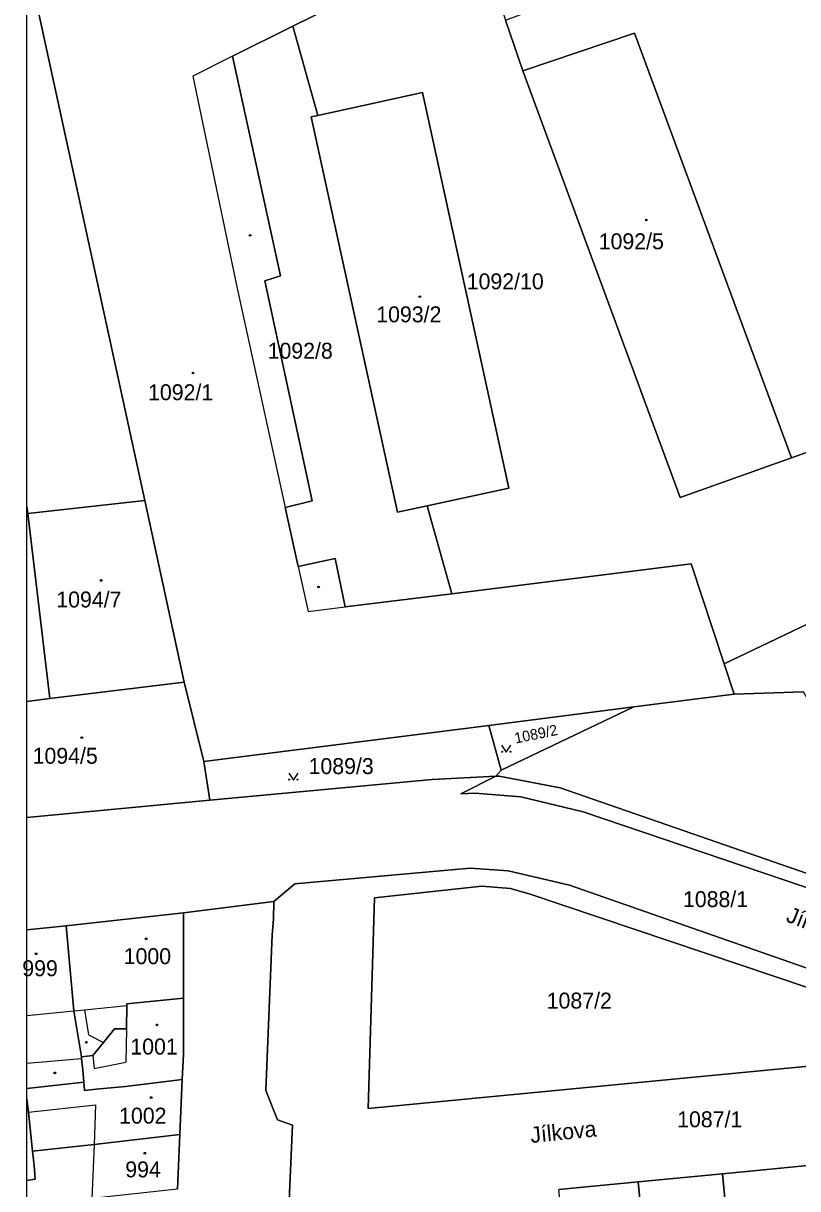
# Model space of a CAD drawing. Extents: x -596233 to -595156, y -1161235 to -1159375.
# Drawn here: x -596228.6 to -596146, y -1160887.6 to -1160763.3 of the extents above; entities that cross this region are included whole.
import ezdxf

# ---------------------------------------------------------------- set-up
doc = ezdxf.new("R2010")
doc.units = 0
for name, color, linetype in [('KN_CAR_KR', 7, 'Continuous'), ('KN_KULTURY', 7, 'Continuous'), ('KN_PARC_CIS_POZ', 7, 'Continuous'), ('KN_PARC_CIS_STAV', 7, 'Continuous'), ('KN_PARC_PLOCHA', 7, 'Continuous'), ('KN_ULICE', 7, 'Continuous'), ('parcely_l', 7, 'Continuous')]:
    doc.layers.add(name, color=color, linetype=linetype)

msp = doc.modelspace()

# ---------------------------------------------------------------- linework, layer by layer
at = {"layer": 'KN_CAR_KR'}
for points in [[(-596206.28, -1160766.77), (-596210.51, -1160768.91)], [(-596210.51, -1160768.91), (-596205.83, -1160791.38)], [(-596205.83, -1160791.38), (-596200.64, -1160814.91)], [(-596199.26, -1160821.19), (-596198.19, -1160826.01)], [(-596198.19, -1160826.01), (-596194.26, -1160825.52)], [(-596228.2196, -1160869.0741), (-596223.22, -1160868.58)], [(-596223.22, -1160868.58), (-596222.08, -1160868.47)], [(-596222.08, -1160868.47), (-596217.55, -1160868.01)], [(-596222.08, -1160868.47), (-596221.63, -1160871.15)], [(-596217.59, -1160870.52), (-596217.65, -1160874.08)], [(-596221.63, -1160871.15), (-596220.05, -1160871.97)], [(-596221.17, -1160873.36), (-596221.03, -1160874.75)], [(-596228.2196, -1160874.1739), (-596222.38, -1160873.66)], [(-596221.03, -1160874.75), (-596217.65, -1160874.08)], [(-596228.06, -1160879.39), (-596220.89, -1160878.61)], [(-596220.89, -1160878.61), (-596221.05, -1160882.84)], [(-596221.05, -1160882.84), (-596221.27, -1160888.59)]]:
    msp.add_lwpolyline(points, dxfattribs=at)
at = {"layer": 'KN_KULTURY'}
for points in [[(-596177.5618, -1160840.2616), (-596177.0618, -1160841.0116), (-596176.5618, -1160840.2616)], [(-596200.2818, -1160843.2316), (-596199.7818, -1160843.9816), (-596199.2818, -1160843.2316)]]:
    msp.add_lwpolyline(points, dxfattribs=at)
for centre, radius in [((-596162.12, -1160784.25), 0.09), ((-596162.12, -1160784.25), 0.0398), ((-596204.39, -1160785.89), 0.09), ((-596204.39, -1160785.89), 0.0398), ((-596186.29, -1160792.43), 0.09), ((-596186.29, -1160792.43), 0.0398), ((-596210.49, -1160800.57), 0.09), ((-596210.49, -1160800.57), 0.0398), ((-596220.3, -1160822.69), 0.09), ((-596220.3, -1160822.69), 0.0398), ((-596197.09, -1160823.39), 0.09), ((-596197.09, -1160823.39), 0.0398), ((-596222.36, -1160839.45), 0.09), ((-596222.36, -1160839.45), 0.0398), ((-596177.512, -1160840.9614), 0.05), ((-596176.6126, -1160840.9614), 0.05), ((-596200.232, -1160843.9314), 0.05), ((-596199.3326, -1160843.9314), 0.05), ((-596215.48, -1160860.91), 0.09), ((-596215.48, -1160860.91), 0.0398), ((-596227.23, -1160862.51), 0.09), ((-596227.23, -1160862.51), 0.0398), ((-596214.33, -1160870.09), 0.09), ((-596214.33, -1160870.09), 0.0398), ((-596221.87, -1160871.95), 0.09), ((-596221.87, -1160871.95), 0.0398), ((-596225.23, -1160875.21), 0.09), ((-596225.23, -1160875.21), 0.0398), ((-596214.95, -1160877.84), 0.09), ((-596214.95, -1160877.84), 0.0398), ((-596215.64, -1160883.78), 0.09), ((-596215.64, -1160883.78), 0.0398)]:
    msp.add_circle(centre, radius, dxfattribs=at)
at = {"layer": 'KN_PARC_PLOCHA'}
for points in [[(-596180.21, -1160753.92), (-596199.82, -1160763.59), (-596206.28, -1160766.77), (-596201.14, -1160790.21), (-596202.84, -1160790.73), (-596197.78, -1160814.19), (-596200.64, -1160814.91), (-596199.26, -1160821.19), (-596195.33, -1160820.35), (-596194.26, -1160825.52), (-596182.87, -1160824.1), (-596157.33, -1160820.92), (-596153.81, -1160831.58), (-596152.74, -1160834.82), (-596163.44, -1160836.18), (-596178.93, -1160838.15), (-596209.35, -1160842.01), (-596211.43, -1160833.55), (-596215.64, -1160814.18), (-596227.22, -1160760.93), (-596184.9, -1160740.16)], [(-596118.75, -1160799.6), (-596120.58, -1160800.23), (-596139.2, -1160806.93), (-596146.64, -1160809.6), (-596163.39, -1160764.31), (-596175.3, -1160768.35), (-596177.14, -1160762.95), (-596137.5, -1160748.21)], [(-596177.14, -1160762.95), (-596175.3, -1160768.35), (-596158.5, -1160813.85), (-596146.64, -1160809.6), (-596139.2, -1160806.93), (-596134.62, -1160819.7), (-596133.78, -1160822.01), (-596153.81, -1160831.58), (-596157.33, -1160820.92), (-596182.87, -1160824.1), (-596185.5, -1160814.72), (-596176.78, -1160812.84), (-596185.99, -1160770.64), (-596197.16, -1160773.1), (-596199.82, -1160763.59), (-596180.21, -1160753.92)], [(-596215.64, -1160814.18), (-596228.13, -1160815.55), (-596228.2196, -1160814.7986), (-596228.2196, -1160761.4172), (-596227.22, -1160760.93)], [(-596197.16, -1160773.1), (-596197.88, -1160773.26), (-596188.68, -1160815.4), (-596185.5, -1160814.72), (-596182.87, -1160824.1), (-596194.26, -1160825.52), (-596195.33, -1160820.35), (-596199.26, -1160821.19), (-596200.64, -1160814.91), (-596197.78, -1160814.19), (-596202.84, -1160790.73), (-596201.14, -1160790.21), (-596206.28, -1160766.77), (-596199.82, -1160763.59)], [(-596146.64, -1160809.6), (-596158.5, -1160813.85), (-596175.3, -1160768.35), (-596163.39, -1160764.31)], [(-596185.5, -1160814.72), (-596188.68, -1160815.4), (-596197.88, -1160773.26), (-596197.16, -1160773.1), (-596185.99, -1160770.64), (-596176.78, -1160812.84)], [(-596228.13, -1160815.55), (-596225.77, -1160835.29), (-596228.2196, -1160835.5849), (-596228.2196, -1160814.7986)], [(-596211.43, -1160833.55), (-596225.47, -1160835.25), (-596225.77, -1160835.29), (-596228.13, -1160815.55), (-596215.64, -1160814.18)], [(-596123.17, -1160851.1), (-596127.18, -1160852.56), (-596130.63, -1160843.58), (-596131.93, -1160844.08), (-596133.78, -1160839.09), (-596135.21, -1160839.77), (-596136.23, -1160837.76), (-596137.4, -1160838.35), (-596138.4, -1160836.37), (-596139.69, -1160837.02), (-596140.34, -1160835.65), (-596141.7, -1160836.29), (-596142.23, -1160835.17), (-596143.55, -1160835.79), (-596143.73, -1160835.33), (-596144.7, -1160835.71), (-596145.36, -1160834.57), (-596152.74, -1160834.82), (-596153.81, -1160831.58), (-596133.78, -1160822.01)], [(-596209.35, -1160842.01), (-596208.7, -1160846.12), (-596228.2196, -1160847.9797), (-596228.2196, -1160835.5849), (-596225.77, -1160835.29), (-596225.47, -1160835.25), (-596211.43, -1160833.55)], [(-596177.59, -1160842.94), (-596178.93, -1160838.15), (-596163.44, -1160836.18)], [(-596177.59, -1160842.94), (-596178.19, -1160843.57), (-596184.98, -1160843.92), (-596208.7, -1160846.12), (-596209.35, -1160842.01), (-596178.93, -1160838.15)], [(-596107.22, -1160867.02), (-596097.58, -1160870.36), (-596096.48, -1160868.53), (-596096.44, -1160866.67), (-596096.41, -1160865.4), (-596088.92, -1160863.99), (-596087.89, -1160863.76), (-596085.86, -1160874.42), (-596085.49, -1160876), (-596100.34, -1160870.7), (-596107.03, -1160868.29), (-596168.84, -1160847.35), (-596175.49, -1160845.77), (-596180.4, -1160845.39), (-596181.92, -1160845.45), (-596178.19, -1160843.57), (-596177.81, -1160843.55), (-596171.31, -1160844.82)], [(-596138.5, -1160873.88), (-596191.79, -1160878.99), (-596191.14, -1160856.53), (-596179.67, -1160855.28), (-596176.6, -1160855.55), (-596174.51, -1160856.16), (-596137.2, -1160868.71), (-596136.41, -1160869.5), (-596136, -1160870.46), (-596135.98, -1160871.59), (-596136.48, -1160872.74), (-596137.35, -1160873.52)], [(-596138.5, -1160873.88), (-596137.35, -1160873.52), (-596136.48, -1160872.74), (-596135.98, -1160871.59), (-596136, -1160870.46), (-596136.41, -1160869.5), (-596137.2, -1160868.71), (-596174.51, -1160856.16), (-596176.6, -1160855.55), (-596179.67, -1160855.28), (-596191.14, -1160856.53), (-596191.79, -1160878.99)], [(-596211.52, -1160867.25), (-596217.55, -1160867.86), (-596217.55, -1160868.01), (-596217.59, -1160870.52), (-596218.88, -1160870.51), (-596220.05, -1160871.97), (-596221.17, -1160873.36), (-596222.4, -1160873.49), (-596223.22, -1160868.58), (-596224.04, -1160859.54), (-596211.52, -1160858.13)], [(-596222.4, -1160873.49), (-596222.38, -1160873.66), (-596222.25, -1160874.88), (-596222.14, -1160876.21), (-596228.2196, -1160876.867), (-596228.2196, -1160859.9532), (-596224.04, -1160859.54), (-596223.22, -1160868.58)], [(-596211.64, -1160875.91), (-596217.7, -1160876.67), (-596220.83, -1160876.96), (-596222.07, -1160877.07), (-596222.14, -1160876.21), (-596222.25, -1160874.88), (-596222.38, -1160873.66), (-596222.4, -1160873.49), (-596221.17, -1160873.36), (-596220.05, -1160871.97), (-596218.88, -1160870.51), (-596217.59, -1160870.52), (-596217.55, -1160868.01), (-596217.55, -1160867.86), (-596211.52, -1160867.25), (-596211.52, -1160873.26)], [(-596211.9, -1160881.77), (-596221.05, -1160882.84), (-596227.6, -1160883.55), (-596228.06, -1160879.39), (-596228.2196, -1160877.9593), (-596228.2196, -1160876.867), (-596222.14, -1160876.21), (-596222.07, -1160877.07), (-596220.83, -1160876.96), (-596217.7, -1160876.67), (-596211.64, -1160875.91)], [(-596227.6, -1160883.55), (-596227.43, -1160885.09), (-596227.34, -1160886.55), (-596228.2196, -1160886.6772), (-596228.2196, -1160877.9593), (-596228.06, -1160879.39)], [(-596212.16, -1160887.6), (-596221.27, -1160888.59), (-596227.36, -1160889.47), (-596228.2196, -1160889.5456), (-596228.2196, -1160886.6772), (-596227.34, -1160886.55), (-596227.43, -1160885.09), (-596227.6, -1160883.55), (-596221.05, -1160882.84), (-596211.9, -1160881.77)], [(-596137.68, -1160903.28), (-596137.46, -1160905.73), (-596137.39, -1160906.48), (-596144.44, -1160906.38), (-596144.93, -1160901.29), (-596145.14, -1160899.13), (-596145.03, -1160899.12), (-596145.23, -1160897.26), (-596149.52, -1160897.65), (-596149.91, -1160901.78), (-596153.2, -1160902.09), (-596152.84, -1160897.91), (-596153.99, -1160885.97), (-596139.42, -1160884.56), (-596138.13, -1160898.4)], [(-596153.2, -1160902.09), (-596153.22, -1160902.33), (-596162.22, -1160902.92), (-596161.81, -1160898.64), (-596163, -1160886.84), (-596153.99, -1160885.97), (-596152.84, -1160897.91)], [(-596162.22, -1160902.92), (-596169.96, -1160903.19), (-596170.33, -1160899.4), (-596171.46, -1160887.66), (-596163, -1160886.84), (-596161.81, -1160898.64)]]:
    msp.add_lwpolyline(points, close=True, dxfattribs=at)
for points in [[(-596107.22, -1160867.02), (-596171.31, -1160844.82), (-596177.81, -1160843.55), (-596178.19, -1160843.57), (-596177.59, -1160842.94), (-596163.44, -1160836.18), (-596152.74, -1160834.82), (-596145.36, -1160834.57)], [(-596134.51, -1160867.71), (-596170.3, -1160855.19), (-596176.85, -1160853.65), (-596180.91, -1160853.37), (-596199.63, -1160855.05), (-596201.86, -1160856.94), (-596211.52, -1160858.13), (-596224.04, -1160859.54), (-596228.2196, -1160859.9532), (-596228.2196, -1160847.9797), (-596208.7, -1160846.12), (-596184.98, -1160843.92), (-596178.19, -1160843.57), (-596181.92, -1160845.45), (-596180.4, -1160845.39), (-596175.49, -1160845.77), (-596168.84, -1160847.35), (-596107.03, -1160868.29)], [(-596200.45, -1160893.61), (-596199.88, -1160880.8), (-596201.49, -1160880.22), (-596202.73, -1160877.09), (-596202.04, -1160860.49), (-596201.91, -1160858.83), (-596201.86, -1160856.94), (-596199.63, -1160855.05), (-596180.91, -1160853.37), (-596176.85, -1160853.65), (-596170.3, -1160855.19), (-596134.51, -1160867.71), (-596098.58, -1160879.83), (-596097.34, -1160880.21), (-596095.37, -1160882.37), (-596095.08, -1160886.24), (-596098.74, -1160883.49), (-596101.95, -1160880.79), (-596118.99, -1160882.58), (-596130.41, -1160883.69), (-596139.42, -1160884.56), (-596153.99, -1160885.97), (-596163, -1160886.84), (-596171.46, -1160887.66)], [(-596212.16, -1160887.6), (-596211.9, -1160881.77), (-596211.64, -1160875.91), (-596211.52, -1160873.26), (-596211.52, -1160867.25), (-596211.52, -1160858.13), (-596201.86, -1160856.94), (-596201.91, -1160858.83), (-596202.04, -1160860.49), (-596202.73, -1160877.09), (-596201.49, -1160880.22), (-596199.88, -1160880.8), (-596200.45, -1160893.61)]]:
    msp.add_lwpolyline(points, dxfattribs=at)
at = {"layer": 'parcely_l'}
for points in [[(-596180.21, -1160753.92), (-596199.82, -1160763.59)], [(-596228.2196, -1160814.7986), (-596228.2196, -1160761.4172)], [(-596227.22, -1160760.93), (-596215.64, -1160814.18)], [(-596175.3, -1160768.35), (-596177.14, -1160762.95)], [(-596182.87, -1160824.1), (-596194.26, -1160825.52), (-596195.33, -1160820.35), (-596199.26, -1160821.19), (-596200.64, -1160814.91), (-596197.78, -1160814.19), (-596202.84, -1160790.73), (-596201.14, -1160790.21), (-596206.28, -1160766.77), (-596199.82, -1160763.59)], [(-596199.82, -1160763.59), (-596197.16, -1160773.1)], [(-596175.3, -1160768.35), (-596163.39, -1160764.31), (-596146.64, -1160809.6)], [(-596146.64, -1160809.6), (-596158.5, -1160813.85), (-596175.3, -1160768.35)], [(-596185.5, -1160814.72), (-596176.78, -1160812.84), (-596185.99, -1160770.64), (-596197.16, -1160773.1)], [(-596197.16, -1160773.1), (-596197.88, -1160773.26), (-596188.68, -1160815.4), (-596185.5, -1160814.72)], [(-596139.2, -1160806.93), (-596146.64, -1160809.6)], [(-596228.13, -1160815.55), (-596228.2196, -1160814.7986)], [(-596228.2196, -1160835.5849), (-596228.2196, -1160814.7986)], [(-596215.64, -1160814.18), (-596228.13, -1160815.55)], [(-596211.43, -1160833.55), (-596215.64, -1160814.18)], [(-596185.5, -1160814.72), (-596182.87, -1160824.1)], [(-596225.77, -1160835.29), (-596228.13, -1160815.55)], [(-596182.87, -1160824.1), (-596157.33, -1160820.92), (-596153.81, -1160831.58)], [(-596153.81, -1160831.58), (-596133.78, -1160822.01)], [(-596152.74, -1160834.82), (-596153.81, -1160831.58)], [(-596225.77, -1160835.29), (-596225.47, -1160835.25), (-596211.43, -1160833.55)], [(-596211.43, -1160833.55), (-596209.35, -1160842.01)], [(-596163.44, -1160836.18), (-596152.74, -1160834.82)], [(-596123.17, -1160851.1), (-596127.18, -1160852.56), (-596130.63, -1160843.58), (-596131.93, -1160844.08), (-596133.78, -1160839.09), (-596135.21, -1160839.77), (-596136.23, -1160837.76), (-596137.4, -1160838.35), (-596138.4, -1160836.37), (-596139.69, -1160837.02), (-596140.34, -1160835.65), (-596141.7, -1160836.29), (-596142.23, -1160835.17), (-596143.55, -1160835.79), (-596143.73, -1160835.33), (-596144.7, -1160835.71), (-596145.36, -1160834.57), (-596152.74, -1160834.82)], [(-596228.2196, -1160835.5849), (-596225.77, -1160835.29)], [(-596228.2196, -1160847.9797), (-596228.2196, -1160835.5849)], [(-596178.93, -1160838.15), (-596163.44, -1160836.18)], [(-596163.44, -1160836.18), (-596177.59, -1160842.94)], [(-596209.35, -1160842.01), (-596178.93, -1160838.15)], [(-596177.59, -1160842.94), (-596178.93, -1160838.15)], [(-596209.35, -1160842.01), (-596208.7, -1160846.12)], [(-596178.19, -1160843.57), (-596184.98, -1160843.92), (-596208.7, -1160846.12)], [(-596085.86, -1160874.42), (-596085.49, -1160876), (-596100.34, -1160870.7), (-596107.03, -1160868.29), (-596168.84, -1160847.35), (-596175.49, -1160845.77), (-596180.4, -1160845.39), (-596181.92, -1160845.45), (-596178.19, -1160843.57)], [(-596178.19, -1160843.57), (-596177.59, -1160842.94)], [(-596178.19, -1160843.57), (-596177.81, -1160843.55), (-596171.31, -1160844.82), (-596107.22, -1160867.02)], [(-596208.7, -1160846.12), (-596228.2196, -1160847.9797)], [(-596228.2196, -1160859.9532), (-596228.2196, -1160847.9797)], [(-596201.86, -1160856.94), (-596199.63, -1160855.05), (-596180.91, -1160853.37), (-596176.85, -1160853.65), (-596170.3, -1160855.19), (-596134.51, -1160867.71), (-596098.58, -1160879.83), (-596097.34, -1160880.21), (-596095.37, -1160882.37), (-596095.08, -1160886.24)], [(-596138.5, -1160873.88), (-596137.35, -1160873.52), (-596136.48, -1160872.74), (-596135.98, -1160871.59), (-596136, -1160870.46), (-596136.41, -1160869.5), (-596137.2, -1160868.71), (-596174.51, -1160856.16), (-596176.6, -1160855.55), (-596179.67, -1160855.28), (-596191.14, -1160856.53), (-596191.79, -1160878.99), (-596138.5, -1160873.88)], [(-596211.52, -1160858.13), (-596201.86, -1160856.94)], [(-596201.86, -1160856.94), (-596201.91, -1160858.83), (-596202.04, -1160860.49), (-596202.73, -1160877.09), (-596201.49, -1160880.22), (-596199.88, -1160880.8), (-596200.45, -1160893.61)], [(-596224.04, -1160859.54), (-596211.52, -1160858.13)], [(-596211.52, -1160858.13), (-596211.52, -1160867.25)], [(-596228.2196, -1160859.9532), (-596224.04, -1160859.54)], [(-596222.4, -1160873.49), (-596223.22, -1160868.58), (-596224.04, -1160859.54)], [(-596228.2196, -1160876.867), (-596228.2196, -1160859.9532)], [(-596211.52, -1160867.25), (-596217.55, -1160867.86), (-596217.55, -1160868.01), (-596217.59, -1160870.52), (-596218.88, -1160870.51), (-596220.05, -1160871.97), (-596221.17, -1160873.36), (-596222.4, -1160873.49)], [(-596211.64, -1160875.91), (-596211.52, -1160873.26), (-596211.52, -1160867.25)], [(-596222.4, -1160873.49), (-596222.38, -1160873.66), (-596222.25, -1160874.88), (-596222.14, -1160876.21)], [(-596222.14, -1160876.21), (-596222.07, -1160877.07), (-596220.83, -1160876.96), (-596217.7, -1160876.67), (-596211.64, -1160875.91)], [(-596211.9, -1160881.77), (-596211.64, -1160875.91)], [(-596228.2196, -1160876.867), (-596222.14, -1160876.21)], [(-596228.2196, -1160877.9593), (-596228.2196, -1160876.867)], [(-596227.6, -1160883.55), (-596228.06, -1160879.39), (-596228.2196, -1160877.9593)], [(-596228.2196, -1160886.6772), (-596228.2196, -1160877.9593)], [(-596211.9, -1160881.77), (-596221.05, -1160882.84), (-596227.6, -1160883.55)], [(-596212.16, -1160887.6), (-596211.9, -1160881.77)], [(-596227.6, -1160883.55), (-596227.43, -1160885.09), (-596227.34, -1160886.55), (-596228.2196, -1160886.6772)], [(-596153.99, -1160885.97), (-596139.42, -1160884.56)], [(-596163, -1160886.84), (-596153.99, -1160885.97)], [(-596153.2, -1160902.09), (-596152.84, -1160897.91), (-596153.99, -1160885.97)], [(-596228.2196, -1160889.5456), (-596228.2196, -1160886.6772)], [(-596163, -1160886.84), (-596171.46, -1160887.66)], [(-596162.22, -1160902.92), (-596161.81, -1160898.64), (-596163, -1160886.84)]]:
    msp.add_lwpolyline(points, dxfattribs=at)

# ---------------------------------------------------------------- texts
at = {"layer": 'KN_PARC_CIS_POZ'}
for s, p in [('1092/10', (-596181.2816, -1160791.64)), ('1092/8', (-596202.5266, -1160799.04)), ('1089/3', (-596198.1566, -1160843.34)), ('1088/1', (-596158.2066, -1160857.53)), ('1087/2', (-596172.7466, -1160868.35)), ('1087/1', (-596158.8266, -1160881.01))]:
    msp.add_text(s, height=1.7, dxfattribs=at).set_placement(p)
msp.add_text('1089/2', height=1.14, rotation=11.560951, dxfattribs=at).set_placement((-596176.0644, -1160840.0873))
at = {"layer": 'KN_PARC_CIS_STAV'}
for s, p in [('1092/5', (-596167.1966, -1160787.37)), ('1093/2', (-596190.9366, -1160795.16)), ('1092/1', (-596215.2866, -1160803.47)), ('1094/7', (-596225.0766, -1160825.57)), ('1094/5', (-596227.6066, -1160842.24)), ('1000', (-596217.8866, -1160863.61)), ('999', (-596228.7066, -1160864.9)), ('1001', (-596217.1766, -1160873.25)), ('1002', (-596218.3766, -1160880.62)), ('994', (-596217.7166, -1160886.35))]:
    msp.add_text(s, height=1.7, dxfattribs=at).set_placement(p)
at = {"layer": 'KN_ULICE'}
for rotation, p in [(338.717883, (-596147.3102, -1160859.0232)), (5.715959, (-596174.4137, -1160882.6902))]:
    msp.add_text('Jílkova', height=1.7, rotation=rotation, dxfattribs=at).set_placement(p)

doc.saveas('drawing.dxf')
